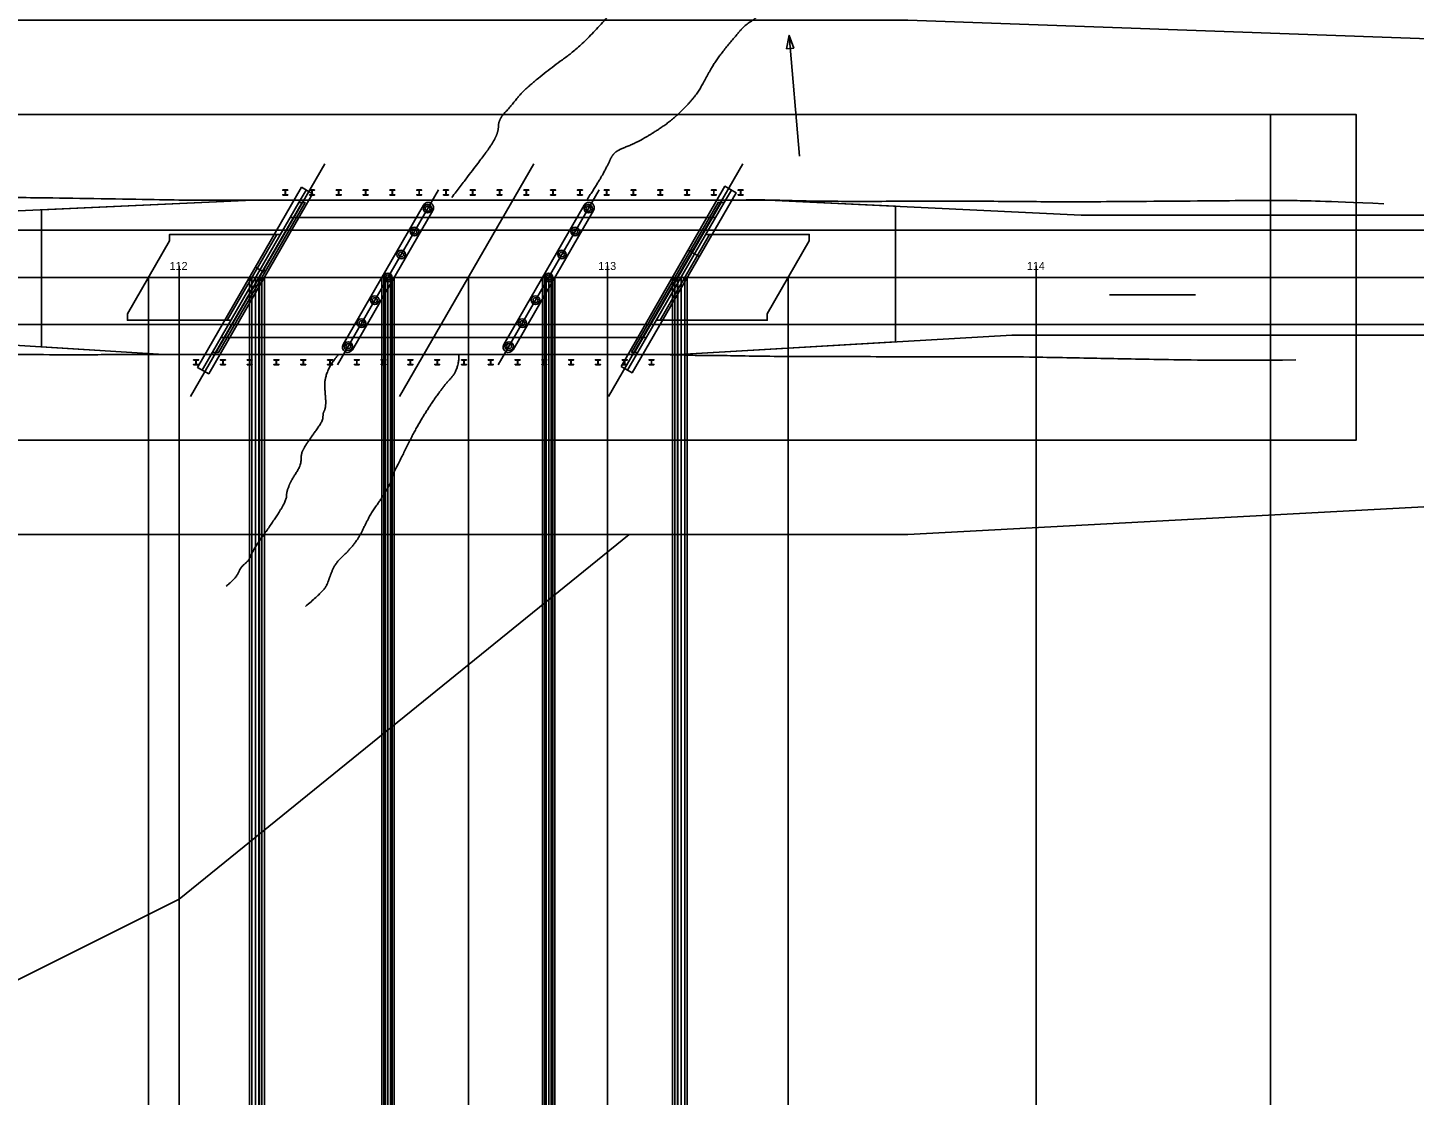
# Model space of a CAD drawing. Extents: x -1300 to 1299, y -770 to 1120.
# Drawn here: x 558 to 881.4, y 234.1 to 483.1 of the extents above; entities that cross this region are included whole.
import ezdxf

# ---------------------------------------------------------------- set-up
doc = ezdxf.new("R2010")
doc.units = 0
for name, color, linetype in [('BR_X_Gen_Approach_Slab', 7, 'Continuous'), ('BR_X_Slab_Centerline', 7, 'Continuous'), ('BR_X_Slab_Const_Joint', 7, 'Continuous'), ('BR_X_Slab_Object', 7, 'Continuous'), ('BR_X_Sub_Centerline', 7, 'Continuous'), ('BR_X_Sub_Deep_Object', 7, 'Continuous'), ('BR_X_Sub_Object', 7, 'Continuous'), ('GE_X_CL_20', 7, 'Continuous'), ('HY_X_Water_Edge', 7, 'Continuous'), ('MD_P_CONST_LIMITS', 7, 'Continuous'), ('PM_P_CL_Dashed', 7, 'Continuous'), ('PM_X_CL_Dashed', 7, 'Continuous'), ('PM_X_Edge_Line', 7, 'Continuous'), ('PV_P_Shoulder_Rumble_Strip', 7, 'Continuous'), ('PV_X_EOP', 7, 'Continuous'), ('RD_X_GR_Lt', 7, 'Continuous'), ('RD_X_GR_Rt', 7, 'Continuous'), ('RW_X_Esmt_CH', 7, 'Continuous'), ('RW_X_Fee_RW', 7, 'Continuous'), ('SC_Scratch1', 7, 'Continuous'), ('SC_Scratch2', 7, 'Continuous')]:
    doc.layers.add(name, color=color, linetype=linetype)

msp = doc.modelspace()

# ---------------------------------------------------------------- linework, layer by layer
at = {"layer": 'BR_X_Gen_Approach_Slab'}
for points in [[(616.92, 434.92), (591.06, 434.92), (591.06, 433.42), (581.24, 416.41), (581.24, 414.91), (605.37, 414.91)], [(716.16, 434.92), (740.3, 434.92), (740.3, 433.42), (730.48, 416.41), (730.48, 414.91), (704.61, 414.91)]]:
    msp.add_lwpolyline(points, dxfattribs=at)
at = {"layer": 'BR_X_Slab_Centerline'}
msp.add_line((676.06, 451.41), (644.72, 397.13), dxfattribs=at)
at = {"layer": 'BR_X_Slab_Const_Joint'}
for p, q in [((619.23, 438.91), (718.47, 438.91)), ((702.3, 410.91), (603.06, 410.91))]:
    msp.add_line(p, q, dxfattribs=at)
at = {"layer": 'BR_X_Slab_Object'}
for points in [[(617.46, 444.11), (617.46, 444.19), (618, 444.19), (618, 445.22), (617.46, 445.22), (617.46, 445.3), (618.61, 445.3), (618.61, 445.22), (618.07, 445.22), (618.07, 444.19), (618.61, 444.19), (618.61, 444.11)], [(623.71, 444.11), (623.71, 444.19), (624.25, 444.19), (624.25, 445.22), (623.71, 445.22), (623.71, 445.3), (624.86, 445.3), (624.86, 445.22), (624.32, 445.22), (624.32, 444.19), (624.86, 444.19), (624.86, 444.11)], [(629.96, 444.11), (629.96, 444.19), (630.5, 444.19), (630.5, 445.22), (629.96, 445.22), (629.96, 445.3), (631.11, 445.3), (631.11, 445.22), (630.57, 445.22), (630.57, 444.19), (631.11, 444.19), (631.11, 444.11)], [(636.21, 444.11), (636.21, 444.19), (636.75, 444.19), (636.75, 445.22), (636.21, 445.22), (636.21, 445.3), (637.36, 445.3), (637.36, 445.22), (636.82, 445.22), (636.82, 444.19), (637.36, 444.19), (637.36, 444.11)], [(642.46, 444.11), (642.46, 444.19), (643, 444.19), (643, 445.22), (642.46, 445.22), (642.46, 445.3), (643.61, 445.3), (643.61, 445.22), (643.07, 445.22), (643.07, 444.19), (643.61, 444.19), (643.61, 444.11)], [(648.71, 444.11), (648.71, 444.19), (649.25, 444.19), (649.25, 445.22), (648.71, 445.22), (648.71, 445.3), (649.86, 445.3), (649.86, 445.22), (649.32, 445.22), (649.32, 444.19), (649.86, 444.19), (649.86, 444.11)], [(654.96, 444.11), (654.96, 444.19), (655.5, 444.19), (655.5, 445.22), (654.96, 445.22), (654.96, 445.3), (656.11, 445.3), (656.11, 445.22), (655.57, 445.22), (655.57, 444.19), (656.11, 444.19), (656.11, 444.11)], [(661.21, 444.11), (661.21, 444.19), (661.75, 444.19), (661.75, 445.22), (661.21, 445.22), (661.21, 445.3), (662.36, 445.3), (662.36, 445.22), (661.82, 445.22), (661.82, 444.19), (662.36, 444.19), (662.36, 444.11)], [(667.46, 444.11), (667.46, 444.19), (668, 444.19), (668, 445.22), (667.46, 445.22), (667.46, 445.3), (668.61, 445.3), (668.61, 445.22), (668.07, 445.22), (668.07, 444.19), (668.61, 444.19), (668.61, 444.11)], [(673.71, 444.11), (673.71, 444.19), (674.25, 444.19), (674.25, 445.22), (673.71, 445.22), (673.71, 445.3), (674.86, 445.3), (674.86, 445.22), (674.32, 445.22), (674.32, 444.19), (674.86, 444.19), (674.86, 444.11)], [(679.96, 444.11), (679.96, 444.19), (680.5, 444.19), (680.5, 445.22), (679.96, 445.22), (679.96, 445.3), (681.11, 445.3), (681.11, 445.22), (680.57, 445.22), (680.57, 444.19), (681.11, 444.19), (681.11, 444.11)], [(686.21, 444.11), (686.21, 444.19), (686.75, 444.19), (686.75, 445.22), (686.21, 445.22), (686.21, 445.3), (687.36, 445.3), (687.36, 445.22), (686.82, 445.22), (686.82, 444.19), (687.36, 444.19), (687.36, 444.11)], [(692.46, 444.11), (692.46, 444.19), (693, 444.19), (693, 445.22), (692.46, 445.22), (692.46, 445.3), (693.61, 445.3), (693.61, 445.22), (693.07, 445.22), (693.07, 444.19), (693.61, 444.19), (693.61, 444.11)], [(698.71, 444.11), (698.71, 444.19), (699.25, 444.19), (699.25, 445.22), (698.71, 445.22), (698.71, 445.3), (699.86, 445.3), (699.86, 445.22), (699.32, 445.22), (699.32, 444.19), (699.86, 444.19), (699.86, 444.11)], [(704.96, 444.11), (704.96, 444.19), (705.5, 444.19), (705.5, 445.22), (704.96, 445.22), (704.96, 445.3), (706.11, 445.3), (706.11, 445.22), (705.57, 445.22), (705.57, 444.19), (706.11, 444.19), (706.11, 444.11)], [(711.21, 444.11), (711.21, 444.19), (711.75, 444.19), (711.75, 445.22), (711.21, 445.22), (711.21, 445.3), (712.36, 445.3), (712.36, 445.22), (711.82, 445.22), (711.82, 444.19), (712.36, 444.19), (712.36, 444.11)], [(717.46, 444.11), (717.46, 444.19), (718, 444.19), (718, 445.22), (717.46, 445.22), (717.46, 445.3), (718.61, 445.3), (718.61, 445.22), (718.07, 445.22), (718.07, 444.19), (718.61, 444.19), (718.61, 444.11)], [(723.71, 444.11), (723.71, 444.19), (724.25, 444.19), (724.25, 445.22), (723.71, 445.22), (723.71, 445.3), (724.86, 445.3), (724.86, 445.22), (724.32, 445.22), (724.32, 444.19), (724.86, 444.19), (724.86, 444.11)], [(621.54, 442.91), (600.75, 406.91), (699.99, 406.91), (720.78, 442.91)], [(596.67, 404.52), (596.67, 404.6), (597.21, 404.6), (597.21, 405.63), (596.67, 405.63), (596.67, 405.71), (597.82, 405.71), (597.82, 405.63), (597.28, 405.63), (597.28, 404.6), (597.82, 404.6), (597.82, 404.52)], [(602.92, 404.52), (602.92, 404.6), (603.46, 404.6), (603.46, 405.63), (602.92, 405.63), (602.92, 405.71), (604.07, 405.71), (604.07, 405.63), (603.53, 405.63), (603.53, 404.6), (604.07, 404.6), (604.07, 404.52)], [(609.17, 404.52), (609.17, 404.6), (609.71, 404.6), (609.71, 405.63), (609.17, 405.63), (609.17, 405.71), (610.32, 405.71), (610.32, 405.63), (609.78, 405.63), (609.78, 404.6), (610.32, 404.6), (610.32, 404.52)], [(615.42, 404.52), (615.42, 404.6), (615.96, 404.6), (615.96, 405.63), (615.42, 405.63), (615.42, 405.71), (616.57, 405.71), (616.57, 405.63), (616.03, 405.63), (616.03, 404.6), (616.57, 404.6), (616.57, 404.52)], [(621.67, 404.52), (621.67, 404.6), (622.21, 404.6), (622.21, 405.63), (621.67, 405.63), (621.67, 405.71), (622.82, 405.71), (622.82, 405.63), (622.28, 405.63), (622.28, 404.6), (622.82, 404.6), (622.82, 404.52)], [(627.92, 404.52), (627.92, 404.6), (628.46, 404.6), (628.46, 405.63), (627.92, 405.63), (627.92, 405.71), (629.07, 405.71), (629.07, 405.63), (628.53, 405.63), (628.53, 404.6), (629.07, 404.6), (629.07, 404.52)], [(634.17, 404.52), (634.17, 404.6), (634.71, 404.6), (634.71, 405.63), (634.17, 405.63), (634.17, 405.71), (635.32, 405.71), (635.32, 405.63), (634.78, 405.63), (634.78, 404.6), (635.32, 404.6), (635.32, 404.52)], [(640.42, 404.52), (640.42, 404.6), (640.96, 404.6), (640.96, 405.63), (640.42, 405.63), (640.42, 405.71), (641.57, 405.71), (641.57, 405.63), (641.03, 405.63), (641.03, 404.6), (641.57, 404.6), (641.57, 404.52)], [(646.67, 404.52), (646.67, 404.6), (647.21, 404.6), (647.21, 405.63), (646.67, 405.63), (646.67, 405.71), (647.82, 405.71), (647.82, 405.63), (647.28, 405.63), (647.28, 404.6), (647.82, 404.6), (647.82, 404.52)], [(652.92, 404.52), (652.92, 404.6), (653.46, 404.6), (653.46, 405.63), (652.92, 405.63), (652.92, 405.71), (654.07, 405.71), (654.07, 405.63), (653.53, 405.63), (653.53, 404.6), (654.07, 404.6), (654.07, 404.52)], [(659.17, 404.52), (659.17, 404.6), (659.71, 404.6), (659.71, 405.63), (659.17, 405.63), (659.17, 405.71), (660.32, 405.71), (660.32, 405.63), (659.78, 405.63), (659.78, 404.6), (660.32, 404.6), (660.32, 404.52)], [(665.42, 404.52), (665.42, 404.6), (665.96, 404.6), (665.96, 405.63), (665.42, 405.63), (665.42, 405.71), (666.57, 405.71), (666.57, 405.63), (666.03, 405.63), (666.03, 404.6), (666.57, 404.6), (666.57, 404.52)], [(671.67, 404.52), (671.67, 404.6), (672.21, 404.6), (672.21, 405.63), (671.67, 405.63), (671.67, 405.71), (672.82, 405.71), (672.82, 405.63), (672.28, 405.63), (672.28, 404.6), (672.82, 404.6), (672.82, 404.52)], [(677.92, 404.52), (677.92, 404.6), (678.46, 404.6), (678.46, 405.63), (677.92, 405.63), (677.92, 405.71), (679.07, 405.71), (679.07, 405.63), (678.53, 405.63), (678.53, 404.6), (679.07, 404.6), (679.07, 404.52)], [(684.17, 404.52), (684.17, 404.6), (684.71, 404.6), (684.71, 405.63), (684.17, 405.63), (684.17, 405.71), (685.32, 405.71), (685.32, 405.63), (684.78, 405.63), (684.78, 404.6), (685.32, 404.6), (685.32, 404.52)], [(690.42, 404.52), (690.42, 404.6), (690.96, 404.6), (690.96, 405.63), (690.42, 405.63), (690.42, 405.71), (691.57, 405.71), (691.57, 405.63), (691.03, 405.63), (691.03, 404.6), (691.57, 404.6), (691.57, 404.52)], [(696.67, 404.52), (696.67, 404.6), (697.21, 404.6), (697.21, 405.63), (696.67, 405.63), (696.67, 405.71), (697.82, 405.71), (697.82, 405.63), (697.28, 405.63), (697.28, 404.6), (697.82, 404.6), (697.82, 404.52)], [(702.92, 404.52), (702.92, 404.6), (703.46, 404.6), (703.46, 405.63), (702.92, 405.63), (702.92, 405.71), (704.07, 405.71), (704.07, 405.63), (703.53, 405.63), (703.53, 404.6), (704.07, 404.6), (704.07, 404.52)]]:
    msp.add_lwpolyline(points, close=True, dxfattribs=at)
at = {"layer": 'BR_X_Sub_Centerline'}
for p, q in [((627.31, 451.41), (595.97, 397.13)), ((693.48, 397.13), (724.82, 451.41)), ((653.81, 445.34), (630.22, 404.49)), ((667.72, 404.49), (691.31, 445.34))]:
    msp.add_line(p, q, dxfattribs=at)
at = {"layer": 'BR_X_Sub_Deep_Object'}
for centre, radius in [((651.26, 440.93), 1), ((651.26, 440.93), 0.583), ((688.76, 440.93), 1), ((688.76, 440.93), 0.583), ((648.18, 435.59), 1), ((648.18, 435.59), 0.583), ((685.68, 435.59), 1), ((685.68, 435.59), 0.583), ((645.1, 430.25), 1), ((645.1, 430.25), 0.583), ((682.6, 430.25), 1), ((682.6, 430.25), 0.583), ((642.01, 424.91), 1), ((642.01, 424.91), 0.583), ((679.51, 424.91), 1), ((679.51, 424.91), 0.583), ((638.93, 419.57), 1), ((676.43, 419.57), 1), ((638.93, 419.57), 0.583), ((676.43, 419.57), 0.583), ((635.85, 414.23), 1), ((635.85, 414.23), 0.583), ((673.35, 414.23), 1), ((673.35, 414.23), 0.583), ((632.76, 408.89), 1), ((632.76, 408.89), 0.583), ((670.26, 408.89), 1), ((670.26, 408.89), 0.583)]:
    msp.add_circle(centre, radius, dxfattribs=at)
at = {"layer": 'BR_X_Sub_Object'}
for p, q in [((622.91, 445.29), (621.54, 442.91)), ((722.15, 445.29), (720.78, 442.91)), ((601.76, 407.41), (621.97, 442.41)), ((631.55, 409.29), (650.31, 441.78)), ((652.48, 440.53), (633.72, 408.04)), ((687.81, 441.78), (669.05, 409.29)), ((671.22, 408.04), (689.98, 440.53)), ((699.56, 407.41), (719.77, 442.41)), ((604.51, 414.91), (616.06, 434.92)), ((717.03, 434.92), (705.48, 414.91)), ((600.75, 406.91), (598.66, 403.29)), ((699.99, 406.91), (697.9, 403.29))]:
    msp.add_line(p, q, dxfattribs=at)
for points in [[(621.83, 445.92), (597.58, 403.92), (600.18, 402.42), (624.43, 444.42)], [(696.38, 404.16), (698.98, 402.66), (723.23, 444.66), (720.63, 446.16)]]:
    msp.add_lwpolyline(points, close=True, dxfattribs=at)
for points in [[(621.25, 442.41), (622.69, 442.41), (602.48, 407.41), (601.04, 407.41)], [(720.49, 442.41), (719.04, 442.41), (698.84, 407.41), (700.28, 407.41)]]:
    msp.add_lwpolyline(points, dxfattribs=at)
for centre, start, end in [((651.39, 441.16), 330, 150), ((688.89, 441.16), 330, 150), ((632.63, 408.66), 150, 330), ((670.13, 408.66), 150, 330)]:
    msp.add_arc(centre, 1.25, start, end, dxfattribs=at)
at = {"layer": 'GE_X_CL_20'}
for p, q in [((391.46, 424.91), (920.48, 424.91)), ((593.26, 424.91), (593.26, 426.24)), ((693.26, 424.91), (693.26, 426.24)), ((793.26, 424.91), (793.26, 426.24))]:
    msp.add_line(p, q, dxfattribs=at)
at = {"layer": 'HY_X_Water_Edge'}
for points in [[(656.9, 443.54), (663.26, 451.85), (666.25, 455.9), (667.78, 458.86), (667.78, 461.69), (670.87, 465.07), (673.38, 468.3), (679.78, 473.6), (687.25, 478.94), (698.5, 491.5), (707.08, 502.26), (714.51, 512.98), (720.93, 523.97), (725.58, 527.83), (731.52, 531.63), (736.56, 534.7), (737.39, 538.72), (740.67, 541.88), (744.13, 544.81), (746.03, 549.48)], [(688.35, 442.91), (691.25, 447.31), (693.36, 451.27), (694.36, 453.51), (695.87, 454.71), (699.69, 456.18), (704.19, 458.77), (708.82, 461.99), (714.19, 467.59), (716.14, 471.47), (719.05, 476.34), (723.74, 481.94), (725.26, 483.72), (728.19, 485.6), (734.07, 490.74), (739.59, 495.75), (745.58, 501.89), (750.16, 505.61), (755.55, 509.08), (757.27, 513.01), (759.89, 513.01), (761.39, 516.83), (764.69, 519.26), (766.68, 522.02), (771.69, 524.57), (777.58, 532.33), (778.34, 535.1), (781.14, 538.81), (783.81, 541.37)], [(630.46, 406.91), (628.55, 404.63), (627.26, 401.21), (627.26, 399.01), (627.54, 395.82), (627.36, 394.12), (626.85, 393.24), (626.85, 391.52), (624.51, 388.23), (622.66, 385.56), (621.73, 383.71), (621.73, 381.03), (619.36, 377.49), (618.34, 374.77), (618.34, 373.18), (616.71, 370.2), (614.05, 366.31), (610.45, 361.19), (609.68, 358.95), (607.67, 357.37), (606.64, 354.84), (604.24, 352.85)], [(658.56, 406.77), (658.56, 403.44), (654.99, 399.57), (651.34, 394.35), (648.08, 388.88), (644.15, 380.81), (643.02, 378.9), (642.6, 376.81), (640.46, 373.26), (637.73, 369.41), (635.31, 364.26), (632.92, 361.21), (629.75, 358.29), (628.35, 354.87), (627.37, 351.98), (622.78, 348.18)]]:
    msp.add_open_spline(points, degree=2, dxfattribs=at)
at = {"layer": 'MD_P_CONST_LIMITS'}
msp.add_lwpolyline([(453.64, 462.91), (867.88, 462.91), (867.88, 386.91), (453.64, 386.91)], close=True, dxfattribs=at)
at = {"layer": 'PM_P_CL_Dashed'}
msp.add_line((473.64, 424.91), (847.88, 424.91), dxfattribs=at)
at = {"layer": 'PM_X_CL_Dashed'}
msp.add_line((847.88, 424.91), (1220.7, 424.91), dxfattribs=at)
at = {"layer": 'PM_X_Edge_Line'}
for p, q in [((391.46, 435.91), (920.48, 435.91)), ((391.46, 413.91), (920.48, 413.91))]:
    msp.add_line(p, q, dxfattribs=at)
at = {"layer": 'PV_P_Shoulder_Rumble_Strip'}
for p, q in [((611.14, 424.91), (193.26, 424.91)), ((710.38, 424.91), (1093.26, 424.91))]:
    msp.add_line(p, q, dxfattribs=at)
at = {"layer": 'PV_X_EOP'}
for points in [[(621.54, 442.91), (610.47, 442.91), (533.45, 439.41), (391.46, 439.41)], [(720.78, 442.91), (730.73, 442.91), (803.71, 439.41), (920.48, 439.41)], [(600.75, 406.91), (589.69, 406.91), (517.28, 411.41), (391.46, 411.41)], [(700.52, 406.91), (709.95, 406.91), (787.54, 411.41), (920.48, 411.41)]]:
    msp.add_lwpolyline(points, dxfattribs=at)
at = {"layer": 'RD_X_GR_Lt'}
for points in [[(725.56, 442.97), (729.87, 443), (735.95, 442.84), (741.78, 442.65), (748.6, 442.65), (756.09, 442.65), (764.39, 442.65), (776.91, 442.74), (793.7, 442.54), (808.18, 442.54), (840.09, 442.82), (853.17, 442.9), (859.85, 442.69), (874.36, 442.1)], [(596, 406.91), (587.6, 406.9), (581.57, 406.91), (574.81, 406.91), (569.65, 406.78), (559.34, 406.93), (545.66, 407.05), (534.45, 407.31), (526.08, 407.31), (520.46, 407.46), (514.42, 407.28), (505.23, 407.39), (481.4, 407.51), (469.35, 407.3), (451.19, 407.23), (444.37, 407.31)]]:
    msp.add_open_spline(points, degree=3, dxfattribs=at)
at = {"layer": 'RD_X_GR_Rt'}
for points in [[(616.46, 442.92), (603.16, 442.96), (595.89, 442.89), (588.44, 443.03), (575.12, 443.26), (561.63, 443.48), (552.94, 443.56), (475.29, 444.16), (463.39, 443.93)], [(704.46, 406.9), (709.72, 406.87), (713.6, 406.7), (716.59, 406.7), (720.56, 406.7), (728.13, 406.49), (735.83, 406.49), (748.75, 406.49), (760.75, 406.35), (763.94, 406.38), (767.55, 406.38), (778.19, 406.38), (783.7, 406.38), (789.91, 406.38), (806.6, 406.05), (821.86, 405.77), (836.46, 405.5), (853.82, 405.65)]]:
    msp.add_open_spline(points, degree=3, dxfattribs=at)
at = {"layer": 'RW_X_Esmt_CH'}
msp.add_lwpolyline([(543.26, 364.91), (513.26, 239.91), (593.26, 279.91), (698.26, 364.91)], dxfattribs=at)
at = {"layer": 'RW_X_Fee_RW'}
for points in [[(193.26, 471.45), (543.26, 484.91), (763.26, 484.91), (1043.26, 474.91)], [(193.26, 378.37), (543.26, 364.91), (763.26, 364.91), (1043.26, 379.91)]]:
    msp.add_lwpolyline(points, dxfattribs=at)
at = {"layer": 'SC_Scratch1'}
for p, q in [((847.88, 412.67), (847.88, 462.91)), ((561.14, 408.68), (561.14, 440.67)), ((561.14, 440.67), (561.14, 408.68)), ((621.54, 442.91), (600.75, 406.91)), ((600.75, 406.91), (621.54, 442.91)), ((720.78, 442.91), (699.99, 406.91)), ((720.78, 442.91), (699.99, 406.91)), ((760.38, 409.84), (760.38, 441.49)), ((760.38, 409.84), (760.38, 441.49)), ((847.88, -369.47), (847.88, 439.29)), ((712.47, 431.03), (712.04, 431.28)), ((713.01, 430.71), (712.47, 431.03)), ((713.14, 431.18), (712.71, 431.43)), ((713.55, 430.4), (713.01, 430.71)), ((713.55, 430.4), (714.2, 430.03)), ((593.26, 426.24), (593.26, 427.58)), ((611.51, 427.04), (611.07, 427.29)), ((612.15, 426.66), (611.51, 427.04)), ((693.26, 426.24), (693.26, 427.58)), ((714.2, 430.03), (714.64, 429.78)), ((793.26, 426.24), (793.26, 427.58)), ((612.15, 426.66), (612.7, 426.35)), ((612.7, 426.35), (613.24, 426.04)), ((613.04, 426.69), (613.47, 426.44)), ((660.76, 424.91), (660.76, -419.48)), ((830.38, 420.85), (810.38, 420.85))]:
    msp.add_line(p, q, dxfattribs=at)
for points in [[(735.58, 481.38), (735, 478.24), (735.84, 478.31), (736.69, 478.38), (735.58, 481.34), (738.02, 453.22)], [(621.54, 442.91), (610.47, 442.91), (561.14, 440.67)], [(760.38, 441.49), (730.73, 442.91), (720.78, 442.91)], [(561.14, 408.68), (589.69, 406.91), (600.75, 406.91)], [(699.99, 406.91), (709.95, 406.91), (760.38, 409.84)]]:
    msp.add_lwpolyline(points, dxfattribs=at)
msp.add_lwpolyline([(621.54, 442.91), (600.75, 406.91), (699.99, 406.91), (720.78, 442.91)], close=True, dxfattribs=at)
at = {"layer": 'SC_Scratch2'}
for p, q in [((586.14, 424.91), (586.14, -375.93)), ((593.26, 424.91), (593.26, -375.93)), ((609.7, 424.91), (609.7, -375.93)), ((610.28, 424.91), (610.28, -375.93)), ((611.14, 424.91), (611.14, -375.93)), ((611.87, 424.91), (611.87, -375.93)), ((612.01, 424.91), (612.01, -375.93)), ((612.59, 424.91), (612.59, -375.93)), ((613.17, 424.91), (613.17, -375.93)), ((640.57, 424.91), (640.57, -375.93)), ((641.01, 424.91), (641.01, -375.93)), ((641.43, 424.91), (641.43, -375.93)), ((642.01, 424.91), (642.01, -375.93)), ((642.6, 424.91), (642.6, -375.93)), ((643.01, 424.91), (643.01, -375.93)), ((643.46, 424.91), (643.46, -375.93)), ((660.76, 424.91), (660.76, -375.93)), ((678.07, 424.91), (678.07, -375.93)), ((678.51, 424.91), (678.51, -375.93)), ((678.93, 424.91), (678.93, -375.93)), ((679.51, 424.91), (679.51, -375.93)), ((680.1, 424.91), (680.1, -375.93)), ((680.51, 424.91), (680.51, -375.93)), ((680.96, 424.91), (680.96, -375.93)), ((693.26, 424.91), (693.26, -375.93)), ((708.36, 424.91), (708.36, -375.93)), ((708.94, 424.91), (708.94, -375.93)), ((709.52, 424.91), (709.52, -375.93)), ((709.66, 424.91), (709.66, -375.93)), ((710.38, 424.91), (710.38, -375.93)), ((711.25, 424.91), (711.25, -375.93)), ((711.83, 424.91), (711.83, -375.93)), ((735.38, 424.91), (735.38, -375.93)), ((793.26, 424.91), (793.26, -375.93))]:
    msp.add_line(p, q, dxfattribs=at)

# ---------------------------------------------------------------- texts
at = {"layer": 'GE_X_CL_20'}
for s, p in [('112', (591.08, 426.64)), ('113', (691.08, 426.64)), ('114', (791.08, 426.64))]:
    msp.add_text(s, height=1.867, dxfattribs=at).set_placement(p)

doc.saveas('drawing.dxf')
